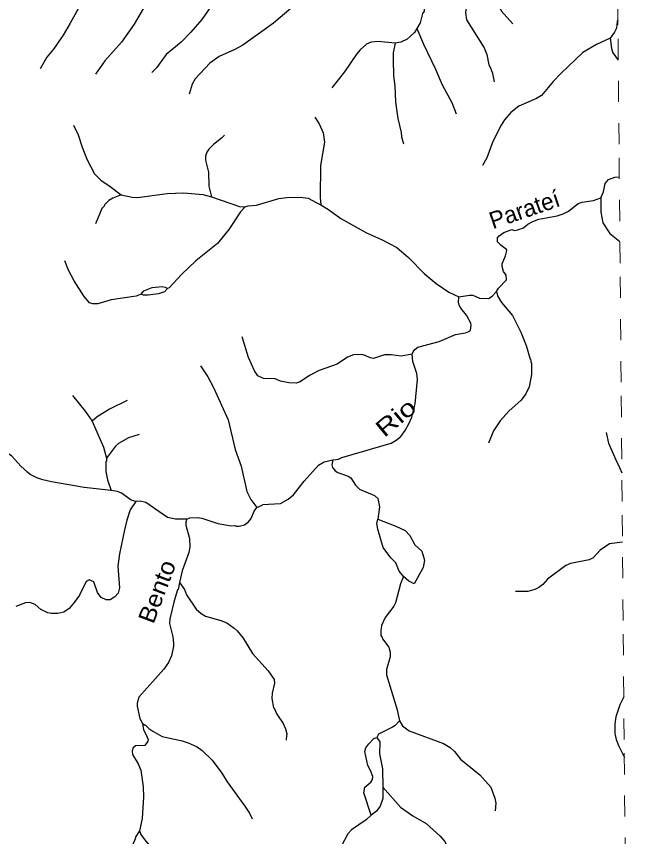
# Model space of a CAD drawing. Extents: x 346.5 to 372.4, y 7400.3 to 7428.2.
# Drawn here: x 369.426 to 372.367, y 7406.883 to 7410.774 of the extents above; entities that cross this region are included whole.
import ezdxf
from ezdxf.enums import TextEntityAlignment as Align

# ---------------------------------------------------------------- set-up
doc = ezdxf.new("R2010")
doc.units = 0
doc.header["$LTSCALE"] = 0.032
doc.linetypes.add('SHORT_DASHED', pattern=[2.7, 1.5, -1.2])
for name, color, linetype, lineweight in [('2', 7, 'Continuous', 25), ('53', 7, 'SHORT_DASHED', 13), ('7', 7, 'Continuous', 25)]:
    doc.layers.add(name, color=color, linetype=linetype, lineweight=lineweight)
doc.layers.add('61', color=7, linetype='Continuous')

msp = doc.modelspace()

# ---------------------------------------------------------------- linework, layer by layer
at = {"layer": '2'}
for points in [[(370.0177, 7409.4562), (370.0309, 7409.4714), (370.0695, 7409.4874), (370.1178, 7409.4921), (370.1321, 7409.4893), (370.1432, 7409.4833), (370.1292, 7409.4666), (370.0998, 7409.4575), (370.0506, 7409.4514), (370.0292, 7409.452)], [(371.1404, 7408.3893), (371.2259, 7408.3565), (371.2696, 7408.3351), (371.2918, 7408.3111), (371.3153, 7408.2674), (371.3485, 7408.2376), (371.3612, 7408.195), (371.3557, 7408.1592), (371.3287, 7408.1099), (371.3124, 7408.0823), (371.2877, 7408.0955), (371.2615, 7408.1174), (371.2413, 7408.1415), (371.2263, 7408.182), (371.2024, 7408.205), (371.166, 7408.2544), (371.1399, 7408.3413), (371.1362, 7408.3687)], [(371.109, 7406.9846), (371.0732, 7407.0915), (371.0779, 7407.1181), (371.1075, 7407.1418), (371.1145, 7407.1543), (371.116, 7407.168), (371.1059, 7407.1968), (371.0934, 7407.2199), (371.0785, 7407.2877), (371.0839, 7407.3051), (371.0969, 7407.3239), (371.1207, 7407.3487), (371.1359, 7407.3538), (371.1499, 7407.3328), (371.1488, 7407.2756), (371.162, 7407.2054), (371.1639, 7407.1173), (371.1637, 7407.0644), (371.1519, 7407.0283), (371.1346, 7407.0037)]]:
    msp.add_lwpolyline(points, close=True, dxfattribs=at)
at = {"layer": '53'}
msp.add_lwpolyline([(372.3673, 7400.5644), (372.3624, 7401.1293), (372.3575, 7401.6942), (372.3526, 7402.2591), (372.3477, 7402.8241), (372.3427, 7403.389), (372.3378, 7403.9539), (372.3329, 7404.5188), (372.328, 7405.0838), (372.3231, 7405.6487), (372.3182, 7406.2136), (372.3133, 7406.7785), (372.3084, 7407.3434), (372.3035, 7407.9084), (372.2986, 7408.4733), (372.2937, 7409.0382), (372.2888, 7409.6031), (372.2839, 7410.168), (372.279, 7410.733), (372.2741, 7411.2979)], dxfattribs=at)
at = {"layer": '7'}
for points in [[(370.4743, 7411.0245), (370.4602, 7411.0049), (370.388, 7410.9342), (370.376, 7410.9127), (370.3665, 7410.8569), (370.3569, 7410.8322), (370.3051, 7410.7589), (370.2541, 7410.6991), (370.2079, 7410.6521), (370.1362, 7410.5931), (370.0915, 7410.5302), (370.0684, 7410.5071)], [(369.826, 7411.011), (369.8088, 7411.0138), (369.7957, 7411.0117), (369.7783, 7410.9956), (369.7616, 7410.9558), (369.7353, 7410.8538), (369.7194, 7410.8091), (369.6819, 7410.7422), (369.6484, 7410.6848), (369.603, 7410.6179), (369.5711, 7410.5804), (369.5393, 7410.5246)], [(370.0553, 7411.0022), (370.062, 7410.9414), (370.0581, 7410.8984), (370.0477, 7410.8554), (370.0286, 7410.8123), (369.9847, 7410.7374), (369.9242, 7410.6513), (369.8453, 7410.5629), (369.8007, 7410.4991)], [(370.9463, 7411.0074), (370.9329, 7411.0046), (370.9156, 7410.9932), (370.8311, 7410.9279), (370.808, 7410.9048), (370.7299, 7410.8131), (370.6454, 7410.7422), (370.4996, 7410.637), (370.4629, 7410.6162), (370.388, 7410.5836), (370.3442, 7410.5525), (370.274, 7410.4768), (370.2597, 7410.4521), (370.2453, 7410.4051)], [(371.6698, 7410.9434), (371.6982, 7410.8617), (371.7253, 7410.7996), (371.7803, 7410.7382)], [(371.5658, 7410.8516), (371.5555, 7410.7916), (371.5611, 7410.7581), (371.644, 7410.6242), (371.6575, 7410.5924), (371.6663, 7410.5445), (371.6759, 7410.527), (371.679, 7410.5119), (371.6822, 7410.5103), (371.6918, 7410.4625)], [(371.3595, 7410.8101), (371.3595, 7410.7983), (371.3523, 7410.7868), (371.3403, 7410.7438), (371.3258, 7410.7156)], [(372.2788, 7410.7578), (372.275, 7410.7497), (372.2718, 7410.7178), (372.2624, 7410.6983), (372.2425, 7410.6702)], [(371.3258, 7410.7156), (371.3134, 7410.697), (371.279, 7410.6649), (371.25, 7410.6508), (371.2218, 7410.6467)], [(371.3258, 7410.7156), (371.3571, 7410.6418), (371.4145, 7410.5238), (371.4447, 7410.4489), (371.491, 7410.366), (371.5125, 7410.311)], [(371.2218, 7410.6467), (371.1419, 7410.6553), (371.1084, 7410.6513), (371.0861, 7410.6418), (371.0558, 7410.6147), (371.0391, 7410.5947), (370.9817, 7410.5103), (370.9228, 7410.4354)], [(371.2218, 7410.6467), (371.2136, 7410.6003), (371.2136, 7410.5685), (371.2152, 7410.4919), (371.2216, 7410.4441), (371.2248, 7410.3676), (371.2344, 7410.2895), (371.2503, 7410.2226), (371.2519, 7410.2026), (371.2623, 7410.1692)], [(372.2425, 7410.6702), (372.1764, 7410.6402), (372.1118, 7410.6019), (372.0082, 7410.5023), (371.9723, 7410.4648), (371.9165, 7410.3987), (371.8934, 7410.3835), (371.8082, 7410.3477), (371.7707, 7410.3174), (371.7412, 7410.2831), (371.7253, 7410.2576), (371.6854, 7410.1795), (371.6567, 7410.103), (371.6368, 7410.0672)], [(372.2425, 7410.6702), (372.2489, 7410.621), (372.2552, 7410.6011), (372.2804, 7410.5656)], [(370.8423, 7410.2951), (370.8622, 7410.264), (370.8805, 7410.221), (370.8869, 7410.1764), (370.8685, 7410.0664), (370.867, 7409.915), (370.8703, 7409.8797)], [(369.6971, 7410.2584), (369.7186, 7410.2114), (369.7377, 7410.154), (369.7624, 7410.0935), (369.7967, 7410.0273), (369.8261, 7409.997), (369.8716, 7409.9667), (369.9225, 7409.9269)], [(370.4127, 7410.2106), (370.3992, 7410.1963), (370.3609, 7410.1668), (370.3394, 7410.1437), (370.3298, 7410.1301), (370.3234, 7410.111), (370.3226, 7410.0919), (370.337, 7410.0345), (370.3386, 7409.9691), (370.3512, 7409.9181)], [(372.1984, 7409.9134), (372.2106, 7409.9412), (372.2186, 7409.9803), (372.2337, 7409.9994), (372.264, 7410.0106), (372.2852, 7410.0132)], [(369.9225, 7409.9269), (369.9752, 7409.9165), (370.0007, 7409.9149), (370.141, 7409.9333), (370.2206, 7409.9373), (370.3099, 7409.9285), (370.3512, 7409.9181)], [(369.9225, 7409.9269), (369.8835, 7409.9117), (369.8644, 7409.8998), (369.8437, 7409.8791), (369.8429, 7409.8743), (369.8309, 7409.8624), (369.8007, 7409.7898)], [(370.3512, 7409.9181), (370.4836, 7409.8726), (370.5111, 7409.8705)], [(370.5111, 7409.8705), (370.5256, 7409.8747), (370.5649, 7409.8783), (370.6701, 7409.9094), (370.7084, 7409.9141), (370.7721, 7409.9165), (370.8104, 7409.9109), (370.8486, 7409.8902), (370.8703, 7409.8797)], [(371.7022, 7409.4688), (371.7118, 7409.484), (371.7508, 7409.5237), (371.7484, 7409.5468), (371.7356, 7409.5643), (371.73, 7409.5866), (371.73, 7409.5994), (371.746, 7409.6376), (371.7524, 7409.6631), (371.75, 7409.6687), (371.7245, 7409.6862), (371.7077, 7409.7038), (371.7077, 7409.7237), (371.7149, 7409.7324), (371.738, 7409.7492), (371.7763, 7409.7635), (371.7882, 7409.7587), (371.8034, 7409.7611), (371.8305, 7409.7715), (371.852, 7409.7882), (371.8751, 7409.801), (371.9038, 7409.8113), (371.9899, 7409.8281), (372.0186, 7409.8368), (372.0448, 7409.8496), (372.0895, 7409.8855), (372.1094, 7409.8926), (372.1636, 7409.8998), (372.1984, 7409.9134)], [(372.1984, 7409.9134), (372.1971, 7409.8448), (372.2074, 7409.7946), (372.2401, 7409.7436), (372.2879, 7409.7053)], [(370.5111, 7409.8705), (370.4884, 7409.8464), (370.4342, 7409.7635), (370.3792, 7409.6958), (370.2772, 7409.6137), (370.2087, 7409.5491), (370.1505, 7409.4862), (370.1432, 7409.4833)], [(370.8703, 7409.8797), (370.9065, 7409.858), (370.9642, 7409.8145), (371.0861, 7409.7476), (371.1579, 7409.7157), (371.2296, 7409.6782), (371.2854, 7409.6304), (371.3603, 7409.5547), (371.4176, 7409.5069), (371.4766, 7409.4663), (371.5244, 7409.4437)], [(370.0177, 7409.4562), (369.9943, 7409.4471), (369.8764, 7409.4296), (369.8126, 7409.4105), (369.7887, 7409.4105), (369.7736, 7409.4145), (369.748, 7409.4448), (369.7002, 7409.5197), (369.6739, 7409.5707), (369.6564, 7409.6145)], [(371.5244, 7409.4437), (371.5755, 7409.4519), (371.5914, 7409.4511), (371.6217, 7409.4376), (371.6647, 7409.436), (371.683, 7409.4471), (371.7022, 7409.4688)], [(371.7022, 7409.4688), (371.7083, 7409.4488), (371.7261, 7409.4169), (371.7795, 7409.3555), (371.8177, 7409.2758), (371.8432, 7409.212), (371.8623, 7409.1475), (371.8655, 7409.1443), (371.8655, 7409.1331), (371.8687, 7409.13), (371.8687, 7409.075), (371.8576, 7409.016), (371.8416, 7408.9841), (371.8193, 7408.9538), (371.7611, 7408.9012), (371.7197, 7408.8558), (371.6886, 7408.8072), (371.6647, 7408.749)], [(371.3036, 7409.1719), (371.3071, 7409.183), (371.3153, 7409.1933), (371.33, 7409.2049), (371.4304, 7409.232), (371.5085, 7409.2654), (371.5563, 7409.2734), (371.5723, 7409.279), (371.5794, 7409.2854), (371.5834, 7409.3093), (371.5818, 7409.318), (371.5611, 7409.3571), (371.5332, 7409.389), (371.526, 7409.4033), (371.5228, 7409.4177), (371.5244, 7409.4437)], [(371.3036, 7409.1719), (371.2503, 7409.1626), (371.2041, 7409.169), (371.1722, 7409.1682), (371.1196, 7409.1515), (371.1045, 7409.1539), (371.0798, 7409.1658), (371.0638, 7409.1698), (371.0256, 7409.169), (370.9969, 7409.1578), (370.9475, 7409.1244), (370.8614, 7409.0933), (370.816, 7409.071), (370.7713, 7409.0407), (370.753, 7409.0343), (370.7179, 7409.0351), (370.6781, 7409.0439), (370.6542, 7409.0542), (370.5984, 7409.0558), (370.5713, 7409.0686), (370.5554, 7409.0925), (370.5267, 7409.1563), (370.4964, 7409.2543)], [(370.9261, 7408.6697), (370.953, 7408.6738), (370.9698, 7408.6813), (371.2041, 7408.7498), (371.228, 7408.7633), (371.2487, 7408.7817), (371.2702, 7408.8088), (371.2877, 7408.8407), (371.3013, 7408.8725), (371.3172, 7408.9363), (371.3284, 7409.0511), (371.3252, 7409.0798), (371.3061, 7409.1371), (371.3036, 7409.1719)], [(370.2987, 7409.1156), (370.3338, 7409.0638), (370.3617, 7409.0128), (370.431, 7408.8598), (370.4637, 7408.7195), (370.4916, 7408.6398), (370.5187, 7408.5203), (370.5378, 7408.482), (370.5668, 7408.4441)], [(369.6931, 7408.9754), (369.752, 7408.9012), (369.7849, 7408.8538)], [(369.9521, 7408.9514), (369.8676, 7408.91), (369.8094, 7408.8741), (369.7849, 7408.8538)], [(369.7849, 7408.8538), (369.8389, 7408.7307), (369.8539, 7408.6781)], [(370.0079, 7408.7905), (369.9577, 7408.7753), (369.9106, 7408.7482), (369.8963, 7408.7347), (369.8539, 7408.6781)], [(372.2226, 7408.8), (372.2337, 7408.7498), (372.2681, 7408.6698), (372.2857, 7408.6334), (372.2974, 7408.6091)], [(369.8762, 7408.5251), (369.7473, 7408.5386), (369.5927, 7408.5657), (369.5512, 7408.5753), (369.5225, 7408.5856), (369.4922, 7408.6008), (369.4787, 7408.6119), (369.4476, 7408.6406), (369.4054, 7408.6876), (369.3775, 7408.7068), (369.3479, 7408.721)], [(369.8539, 7408.6781), (369.8539, 7408.6644), (369.8509, 7408.6621), (369.8501, 7408.6143), (369.8588, 7408.5761), (369.8762, 7408.5251)], [(370.5668, 7408.4441), (370.5923, 7408.4551), (370.5936, 7408.4581), (370.6789, 7408.4637), (370.7148, 7408.4836), (370.7403, 7408.5051), (370.7912, 7408.5697), (370.8582, 7408.6446), (370.8853, 7408.6613), (370.9261, 7408.6697)], [(370.9261, 7408.6697), (370.9227, 7408.647), (370.9251, 7408.6343), (370.9387, 7408.6183), (370.9506, 7408.6095), (371, 7408.5936), (371.0128, 7408.5848), (371.0351, 7408.5506), (371.0534, 7408.5314), (371.1244, 7408.5012), (371.1403, 7408.4876), (371.1475, 7408.447), (371.1404, 7408.3893)], [(369.9928, 7408.4725), (369.9704, 7408.4796), (369.9242, 7408.5123), (369.9051, 7408.5203), (369.8762, 7408.5251)], [(369.9928, 7408.4725), (369.9656, 7408.4326), (369.9497, 7408.3848), (369.9385, 7408.3386), (369.9146, 7408.2238), (369.9066, 7408.1665), (369.9146, 7408.0629), (369.9082, 7408.0373), (369.8939, 7408.0198), (369.8716, 7408.007), (369.8525, 7408.007), (369.8285, 7408.0174), (369.811, 7408.0405), (369.7935, 7408.0923), (369.7712, 7408.1019), (369.7576, 7408.0931), (369.7249, 7408.0278), (369.701, 7407.9943), (369.6771, 7407.9656), (369.6516, 7407.9481), (369.6229, 7407.9409), (369.5911, 7407.9409), (369.5751, 7407.9441), (369.5424, 7407.96), (369.5146, 7407.9839), (369.4906, 7407.9943), (369.4691, 7407.9927), (369.4237, 7407.9752)], [(370.2341, 7408.3892), (370.1808, 7408.3888), (370.1425, 7408.3976), (370.0405, 7408.4685), (370.0128, 7408.4746), (369.9928, 7408.4725)], [(370.2341, 7408.3892), (370.2493, 7408.396), (370.2828, 7408.3968), (370.3051, 7408.3936), (370.3816, 7408.3681), (370.4462, 7408.3577), (370.4629, 7408.3593), (370.4685, 7408.3553), (370.482, 7408.3553), (370.5075, 7408.3617), (370.5267, 7408.376), (370.5402, 7408.392), (370.5538, 7408.4263), (370.5668, 7408.4441)], [(370.2341, 7408.3892), (370.2291, 7408.3764), (370.2294, 7408.3609), (370.2469, 7408.2972), (370.2493, 7408.2557), (370.2437, 7408.2302), (370.2127, 7408.1441), (370.1997, 7408.0888)], [(372.3003, 7408.2805), (372.2385, 7408.2724), (372.1947, 7408.2422), (372.162, 7408.2063), (372.1429, 7408.1959), (372.0536, 7408.1792), (372.0313, 7408.1696), (371.9452, 7408.1051), (371.9221, 7408.0796), (371.9038, 7408.0652), (371.8847, 7408.0557), (371.8512, 7408.0461), (371.793, 7408.0453)], [(371.2615, 7408.1174), (371.2479, 7408.082), (371.224, 7407.9927), (371.2168, 7407.976), (371.1754, 7407.9226), (371.1578, 7407.8843), (371.1539, 7407.8588), (371.1547, 7407.8373), (371.161, 7407.8277), (371.1618, 7407.8206), (371.1921, 7407.7815), (371.1993, 7407.7584), (371.1985, 7407.7361), (371.1817, 7407.6755), (371.1817, 7407.65), (371.232, 7407.4843), (371.2424, 7407.4328)], [(370.1997, 7408.0888), (370.1935, 7408.0557), (370.1903, 7408.0533), (370.1752, 7408.0023), (370.1537, 7407.9162), (370.1529, 7407.8939), (370.168, 7407.8301), (370.1712, 7407.8015), (370.1712, 7407.7871), (370.1617, 7407.7409), (370.1473, 7407.709), (370.1258, 7407.6779), (370.0062, 7407.5448), (369.9983, 7407.5161), (369.9991, 7407.5018), (370.0118, 7407.4428), (370.0242, 7407.4191)], [(370.1997, 7408.0888), (370.2238, 7408.0549), (370.2334, 7408.0294), (370.2788, 7407.9616), (370.3019, 7407.9417), (370.3227, 7407.9289), (370.396, 7407.909), (370.4239, 7407.8979), (370.4597, 7407.8716), (370.4733, 7407.8596), (370.5019, 7407.8238), (370.5458, 7407.7512), (370.6207, 7407.6692), (370.6494, 7407.6285), (370.651, 7407.611), (370.6398, 7407.564), (370.6374, 7407.5385), (370.6462, 7407.4946), (370.6494, 7407.493), (370.6613, 7407.4635), (370.6908, 7407.4205), (370.7028, 7407.395), (370.7084, 7407.3711), (370.706, 7407.3472), (370.7052, 7407.34)], [(372.3066, 7407.547), (372.2871, 7407.5082), (372.2696, 7407.4508), (372.264, 7407.4189), (372.264, 7407.3727), (372.2704, 7407.344), (372.2815, 7407.3153), (372.3092, 7407.2586)], [(370.0242, 7407.4191), (370.0294, 7407.3902), (370.0453, 7407.3599), (370.0517, 7407.3416), (370.0501, 7407.336), (370.0357, 7407.3161), (369.9911, 7407.3145), (369.9792, 7407.3033), (369.9752, 7407.2882), (369.9768, 7407.2723), (370.0039, 7407.2292), (370.0166, 7407.199), (370.0278, 7407.1193), (370.0286, 7407.0715), (370.023, 7406.9694), (370.0101, 7406.9103)], [(370.0242, 7407.4191), (370.0409, 7407.4104), (370.0541, 7407.3958), (370.0732, 7407.383), (370.117, 7407.3575), (370.2127, 7407.3376), (370.2414, 7407.3281), (370.2828, 7407.3089), (370.3067, 7407.2922), (370.3545, 7407.2452), (370.4007, 7407.1846), (370.4262, 7407.1432), (370.5099, 7407.0284), (370.5315, 7406.9941), (370.5442, 7406.967)], [(371.2424, 7407.4328), (371.2224, 7407.4101), (371.2105, 7407.4022), (371.144, 7407.3699), (371.1359, 7407.3538)], [(371.2424, 7407.4328), (371.2567, 7407.4086), (371.2885, 7407.3846), (371.4511, 7407.3249), (371.4838, 7407.3057), (371.5037, 7407.2866), (371.5324, 7407.2507), (371.5571, 7407.23), (371.6232, 7407.1758), (371.6759, 7407.1177), (371.6958, 7407.0651), (371.6998, 7407.0412), (371.6966, 7407.0053)], [(371.1639, 7407.1173), (371.2479, 7407.0236), (371.3069, 7406.9822), (371.369, 7406.9447), (371.436, 7406.8858), (371.4567, 7406.8611), (371.4702, 7406.8363), (371.5165, 7406.775), (371.577, 7406.7064), (371.6942, 7406.5941)], [(371.109, 7406.9846), (371.0845, 7406.963), (371.0152, 7406.9153), (370.9984, 7406.8961), (370.9674, 7406.8387), (370.9554, 7406.7846), (370.9562, 7406.7654), (370.9618, 7406.7272), (370.9698, 7406.7025), (370.9793, 7406.6871)], [(370.0101, 7406.9103), (369.9899, 7406.8783), (369.9919, 7406.8762), (369.9752, 7406.8387), (369.9529, 7406.775), (369.8875, 7406.6634), (369.8756, 7406.653), (369.7855, 7406.6148), (369.7704, 7406.602), (369.7552, 7406.5789), (369.752, 7406.5678), (369.7536, 7406.5407), (369.8429, 7406.4466), (369.8787, 7406.4012), (369.8859, 7406.3877), (369.8827, 7406.3582), (369.8604, 7406.3398), (369.8277, 7406.3247), (369.8156, 7406.3113)], [(370.0101, 7406.9103), (370.0165, 7406.8935), (370.0333, 7406.869), (370.0859, 7406.8069), (370.1346, 7406.7399), (370.1633, 7406.7096), (370.2159, 7406.6738), (370.3107, 7406.6267), (370.3346, 7406.6124), (370.3481, 7406.6004), (370.3673, 7406.5686), (370.3736, 7406.5136), (370.3728, 7406.4833), (370.3816, 7406.453), (370.396, 7406.4243), (370.4247, 7406.3924), (370.4757, 7406.3669), (370.5362, 7406.3247), (370.5848, 7406.2649), (370.6239, 7406.2307)]]:
    msp.add_lwpolyline(points, dxfattribs=at)

# ---------------------------------------------------------------- texts
at = {"layer": '61'}
msp.add_text('Parateí', height=0.08, rotation=18.947, dxfattribs=at).set_placement((371.8486, 7409.8198), align=Align.CENTER)
for s, rotation, width, p in [('Rio', 39.839, 1.3, (371.2509, 7408.84)), ('Bento', 69.27, 1.1, (370.1305, 7408.0316))]:
    msp.add_text(s, height=0.08, rotation=rotation, dxfattribs=dict(at, width=width)).set_placement(p, align=Align.CENTER)

doc.saveas('drawing.dxf')
